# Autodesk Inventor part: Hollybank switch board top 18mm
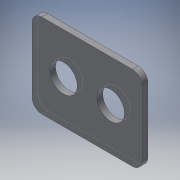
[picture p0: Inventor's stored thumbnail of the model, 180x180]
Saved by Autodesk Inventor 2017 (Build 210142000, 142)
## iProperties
Created: 2015-12
Part Number: Hollybank switch board top 18mm
Material: Generic
Document SubType Name: Modeling
Designer: Designer
Density: 1 g/cm^3
Appearance: Default
Author: Designer
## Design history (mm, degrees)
sketch "Sketch1"
  geometry: L1 (-57, 68.367)-(23, 68.367); L2 (33, 58.367)-(33, -21.633); L3 (23, -31.633)-(-57, -31.633); L4 (-67, -21.633)-(-67, 58.367); L5 (-5, -5)-(-5, 5.367); L6 (-2, 8.367)-(5, 8.367); L7 (8, 11.367)-(8, 33.367); L8 (-39.45, 36.367)-(5, 36.367); L9 (-36.434, 15.879)-(-43.759, 10.649); L10 (-36.443, 20.769)-(-43.792, 25.973); L11 (-40, 13.333)-(-40, 13.33); L12 (-30.528, -8)-(-8, -8); L13 (188, 148.367)-(-72, 148.367); L14 (-112, 108.367)-(-112, -71.633); L15 (-72, -111.633)-(188, -111.633); L16 (228, -71.633)-(228, 108.367); L17 (188, 148.367)-(228, 148.367); L18 (228, 108.367)-(228, 148.367); L19 (228, -71.633)-(228, -111.633); L20 (183, -111.633)-(228, -111.633); L21 (-72, -111.633)-(-112, -111.633); L22 (-112, -111.633)-(-112, -71.633); L23 (-72, 148.367)-(-112, 148.367); L24 (-112, 108.367)-(-112, 148.367); L25 (109.566, 15.879)-(102.241, 10.649); L26 (154, 11.367)-(154, 33.367); L27 (115.472, -8)-(138, -8); L28 (179, 58.367)-(179, -21.633); L29 (169, -31.633)-(89, -31.633); L30 (106, 13.333)-(106, 13.33); L31 (141, -5)-(141, 5.367); L32 (144, 8.367)-(151, 8.367); L33 (89, 68.367)-(169, 68.367); L34 (106.55, 36.367)-(151, 36.367); L35 (79, -21.633)-(79, 58.367); L36 (109.557, 20.769)-(102.208, 25.973); C1 r 1.5 at (-14.993, 41.367); C2 r 1.5 at (-40, 18.33); C3 r 1.5 at (0, 0); C4 r 1.5 at (106, 18.33); C5 r 1.5 at (146, 0); C6 r 1.5 at (131.007, 41.367); A1 r 30 centre (-17, 18.367) between (-41.944, 35.033) and (-44.842, 29.539); A2 r 30 centre (-17, 18.367) between (-44.795, 7.079) and (-32.031, -7.596); A3 r 10 centre (-57, 58.367) between (-57, 68.367) and (-67, 58.367); A4 r 10 centre (23, 58.367) between (33, 58.367) and (23, 68.367); A5 r 10 centre (23, -21.633) between (23, -31.633) and (33, -21.633); A6 r 10 centre (-57, -21.633) between (-67, -21.633) and (-57, -31.633); A7 r 3 centre (-38.177, 18.321) between (-36.434, 15.879) and (-36.443, 20.769); A8 r 3 centre (5, 11.367) between (5, 8.367) and (8, 11.367); A9 r 3 centre (-2, 5.367) between (-2, 8.367) and (-5, 5.367); A10 r 3 centre (-8, -5) between (-8, -8) and (-5, -5); A11 r 3 centre (-42.016, 8.208) between (-43.759, 10.649) and (-44.795, 7.079); A12 r 3 centre (-42.058, 28.422) between (-44.842, 29.539) and (-43.792, 25.973); A13 r 3 centre (-39.45, 33.367) between (-39.45, 36.367) and (-41.944, 35.033); A14 r 3 centre (-30.528, -5) between (-32.031, -7.596) and (-30.528, -8); A15 r 3 centre (5, 33.367) between (8, 33.367) and (5, 36.367); A16 r 30 centre (129, 18.367) between (101.205, 7.079) and (113.969, -7.596); A17 r 3 centre (138, -5) between (138, -8) and (141, -5); A18 r 3 centre (144, 5.367) between (144, 8.367) and (141, 5.367); A19 r 3 centre (151, 11.367) between (151, 8.367) and (154, 11.367); A20 r 10 centre (169, -21.633) between (169, -31.633) and (179, -21.633); A21 r 10 centre (89, -21.633) between (79, -21.633) and (89, -31.633); A22 r 3 centre (151, 33.367) between (154, 33.367) and (151, 36.367); A23 r 10 centre (169, 58.367) between (179, 58.367) and (169, 68.367); A24 r 10 centre (89, 58.367) between (89, 68.367) and (79, 58.367); A25 r 30 centre (129, 18.367) between (104.056, 35.033) and (101.158, 29.539); A26 r 3 centre (115.472, -5) between (113.969, -7.596) and (115.472, -8); A27 r 3 centre (103.984, 8.208) between (102.241, 10.649) and (101.205, 7.079); A28 r 3 centre (107.823, 18.321) between (109.566, 15.879) and (109.557, 20.769); A29 r 3 centre (103.942, 28.422) between (101.158, 29.539) and (102.208, 25.973); A30 r 3 centre (106.55, 33.367) between (106.55, 36.367) and (104.056, 35.033); 24 further points
  constraints: 72 end point, 68 point on circle, 48 tangent, 46 point on line, 36 centre point, 18 equal radius, 16 perpendicular, 7 equal length, 4 horizontal, 2 coincident
  dimensions: "d4" = 3 diameter of C2; "d5" = 3 diameter of C1; "d7" = 100 distance of point (-67, -31.633) point (-67, 68.367); "d8" = 100 distance of point (-67, 68.367) point (33, 68.367); "d17" = 5 distance from line of point (0, 0) L5; "d19" = 25 distance between parallel lines of L2 L7; "d23" = 34 distance of C1.centre C2.centre; "d24" = 44 distance of C1.centre C3.centre; "d25" = 44 distance of point (0, 0) C2.centre; "d26" = 32 distance between parallel lines of L8 L1; "d27" = 47.99344 distance from line of L2 C1.centre; "d28" = 33 distance from line of L2 point (0, 0); "d29" = 27 distance from line of C2.centre L4 (derived); "d30" = 49.96369 distance from line of L3 C2.centre; "d31" = 31.63338 distance from line of L3 C3.centre (derived); "d32" = 30 radius of A2; "d33" = 30 radius of A1; "d34" = 41 distance from line of L7 point (-33, 18.33); "d35" = 8 distance from line of L12 point (0, 0); "d36" = 23.63338 distance between parallel lines of L3 L12 (derived); "d37" = 10 radius of A3; "d40" = 3 radius of A7; "d41" = 3 radius of A8; "d42" = 3 radius of A15; "d61" = 24.98415 distance from line of L4 A11.centre; "d62" = 39.84089 distance from line of L3 A11.centre; "d63" = 28.82318 distance from line of L4 A7.centre; "d64" = 49.95389 distance from line of L3 A7.centre; "d65" = 27.55006 distance from line of L4 A13.centre; "d66" = 28 distance from line of L2 A15.centre; "d67" = 35 distance from line of A15.centre L1; "d68" = 3 diameter of C3; "d69" = 340 distance of L17.end L23.end; "d70" = 260 distance of L19.end L17.end; "d72" = 45 distance between parallel lines of L14 L4; "d117" = 28 distance from line of L2 A8.centre (derived); "d118" = 43 distance from line of L3 A8.centre; "d119" = 3 diameter of C4; "d120" = 3 diameter of C6; "d121" = 100 distance of point (79, -31.633) point (79, 68.367); "d122" = 100 distance of point (79, 68.367) point (179, 68.367); "d123" = 5 distance from line of point (146, 0) L31; "d124" = 25 distance between parallel lines of L28 L26; "d125" = 34 distance of C6.centre C4.centre; "d126" = 44 distance of C6.centre C5.centre; "d127" = 44 distance of point (146, 0) C4.centre; "d128" = 32 distance between parallel lines of L34 L33; "d129" = 47.99344 distance from line of L28 C6.centre; "d130" = 33 distance from line of L28 point (146, 0); "d131" = 27 distance from line of C4.centre L35 (derived); "d132" = 49.96369 distance from line of L29 C4.centre; "d133" = 31.63338 distance from line of L29 C5.centre (derived); "d134" = 30 radius of A16; "d135" = 30 radius of A25; "d136" = 41 distance from line of L26 point (113, 18.33); "d137" = 8 distance from line of L27 point (146, 0); "d138" = 23.63338 distance between parallel lines of L29 L27 (derived); "d139" = 10 radius of A24; "d140" = 3 radius of A28; "d141" = 3 radius of A19; "d142" = 3 radius of A22; "d143" = 24.98415 distance from line of L35 A27.centre; "d144" = 39.84089 distance from line of L29 A27.centre; "d145" = 28.82318 distance from line of L35 A28.centre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
extrude "Extrusion10" new body sketch "Sketch1" distance "d161" = 30; taper "d162" = 0 deg
sketch "Sketch6"
  geometry: L1 (-131.007, 41.367)-(-131.007, 10.217); L2 (14.993, 41.367)-(14.993, 11.919); L3 (112, 148.367)-(112, -111.633) reference; L4 (-131.007, 18.33)-(40, 18.33); C1 r 1.5 at (-131.007, 41.367) reference; C2 r 1.5 at (14.993, 41.367) reference; C3 r 1.5 at (40, 18.33) reference; C4 r 42.5 at (-131.007, 18.33); C5 r 42.5 at (14.993, 18.33); 1 further point
  constraints: 6 end point, 3 point on line, 2 centre point, 2 vertical, 1 coincident, 1 horizontal
  dimensions: "d164" = 85 diameter of C4; "d165" = 85 diameter of C5
extrude "Extrusion11" cut sketch "Sketch6" distance "d166" = 24; taper "d167" = 0 deg
fillet "Fillet1" dims "d168" = 30
sketch "Sketch7"
  geometry: L1 (324.857, 18)-(-75.143, 18); L2 (-75.143, 18)-(-75.143, 38); L3 (-75.143, 38)-(324.857, 38); L4 (324.857, 38)-(324.857, 18); L5 (0, 30)-(280, 30) reference; 1 further point
  constraints: 8 end point, 2 parallel, 1 horizontal, 1 perpendicular
  dimensions: "d169" = 20 distance of L3.end L1.start; "d170" = 400 distance of L1.start L1.end; "d174" = 12 distance between parallel lines of L5 L1
extrude "Extrusion12" cut sketch "Sketch7" stored distance "d172" = 24; taper "d173" = 0 deg
body "Solid4"
other parameters: "d15" = 32, "d16" = 25
